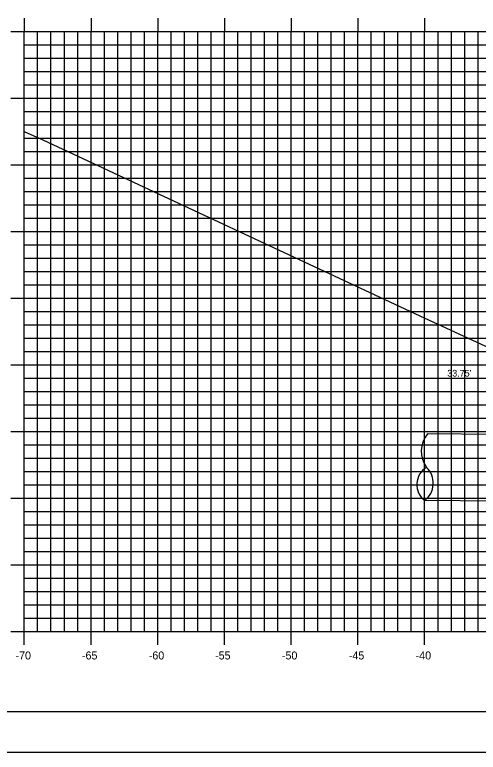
# Model space of a CAD drawing. Extents: x 1170543 to 1177585, y 609599 to 610623.
# Drawn here: x 1175064.6 to 1175099.3, y 609598.8 to 609654.1 of the extents above; entities that cross this region are included whole.
import ezdxf

# ---------------------------------------------------------------- set-up
doc = ezdxf.new("R2010")
doc.units = 0
for name, color, linetype in [('ANNOTATION', 7, 'Continuous'), ('BORDER', 7, 'Continuous'), ('D_Drainage_Text', 7, 'Continuous'), ('H_V ANNOTATION', 7, 'Continuous'), ('MAJOR', 7, 'Continuous'), ('MINOR', 7, 'Continuous'), ('PLOT BOUNDARY', 7, 'Continuous'), ('S_Roadway_Centerline', 7, 'Continuous')]:
    doc.layers.add(name, color=color, linetype=linetype)

msp = doc.modelspace()

# ---------------------------------------------------------------- linework, layer by layer
at = {"layer": 'BORDER'}
msp.add_line((1175060.313, 609601.872), (1175220.313, 609601.872), dxfattribs=at)
at = {"layer": 'D_Drainage_Text'}
for p, q in [((1175111.993, 609622.527), (1175095.525, 609622.687)), ((1175111.945, 609617.527), (1175095.318, 609617.689))]:
    msp.add_line(p, q, dxfattribs=at)
for centre, radius, start, end in [((1175097.136, 609621.381), 2.074, 140.9758, 215.5174), ((1175096.232, 609618.888), 1.508, 121.3337, 232.6687), ((1175094.316, 609618.989), 1.641, 307.6116, 46.3908)]:
    msp.add_arc(centre, radius, start, end, dxfattribs=at)
at = {"layer": 'MAJOR'}
for p, q in [((1175065.313, 609653.874), (1175065.313, 609652.872)), ((1175070.313, 609653.874), (1175070.313, 609652.872)), ((1175075.313, 609653.874), (1175075.313, 609652.872)), ((1175080.313, 609653.874), (1175080.313, 609652.872)), ((1175085.313, 609653.874), (1175085.313, 609652.872)), ((1175090.313, 609653.874), (1175090.313, 609652.872)), ((1175095.313, 609653.874), (1175095.313, 609652.872)), ((1175064.311, 609652.872), (1175065.313, 609652.872)), ((1175065.313, 609652.872), (1175205.313, 609652.872)), ((1175065.313, 609607.872), (1175065.313, 609652.872)), ((1175065.313, 609607.872), (1175065.313, 609652.872)), ((1175065.313, 609652.872), (1175205.313, 609652.872)), ((1175070.313, 609607.872), (1175070.313, 609652.872)), ((1175075.313, 609607.872), (1175075.313, 609652.872)), ((1175080.313, 609607.872), (1175080.313, 609652.872)), ((1175085.313, 609607.872), (1175085.313, 609652.872)), ((1175090.313, 609607.872), (1175090.313, 609652.872)), ((1175095.313, 609607.872), (1175095.313, 609652.872)), ((1175064.311, 609647.872), (1175065.313, 609647.872)), ((1175065.313, 609647.872), (1175205.313, 609647.872)), ((1175064.311, 609642.872), (1175065.313, 609642.872)), ((1175065.313, 609642.872), (1175205.313, 609642.872)), ((1175064.311, 609637.872), (1175065.313, 609637.872)), ((1175065.313, 609637.872), (1175205.313, 609637.872)), ((1175064.311, 609632.872), (1175065.313, 609632.872)), ((1175065.313, 609632.872), (1175205.313, 609632.872)), ((1175064.311, 609627.872), (1175065.313, 609627.872)), ((1175065.313, 609627.872), (1175205.313, 609627.872)), ((1175064.311, 609622.872), (1175065.313, 609622.872)), ((1175065.313, 609622.872), (1175205.313, 609622.872)), ((1175064.311, 609617.872), (1175065.313, 609617.872)), ((1175065.313, 609617.872), (1175205.313, 609617.872)), ((1175064.311, 609612.872), (1175065.313, 609612.872)), ((1175065.313, 609612.872), (1175205.313, 609612.872)), ((1175064.311, 609607.872), (1175065.313, 609607.872)), ((1175065.313, 609607.872), (1175205.313, 609607.872)), ((1175065.313, 609607.872), (1175205.313, 609607.872)), ((1175065.313, 609606.87), (1175065.313, 609607.872)), ((1175070.313, 609606.87), (1175070.313, 609607.872)), ((1175075.313, 609606.87), (1175075.313, 609607.872)), ((1175080.313, 609606.87), (1175080.313, 609607.872)), ((1175085.313, 609606.87), (1175085.313, 609607.872)), ((1175090.313, 609606.87), (1175090.313, 609607.872)), ((1175095.313, 609606.87), (1175095.313, 609607.872))]:
    msp.add_line(p, q, dxfattribs=at)
at = {"layer": 'MINOR'}
for p, q in [((1175066.313, 609607.872), (1175066.313, 609652.872)), ((1175067.313, 609607.872), (1175067.313, 609652.872)), ((1175068.313, 609607.872), (1175068.313, 609652.872)), ((1175069.313, 609607.872), (1175069.313, 609652.872)), ((1175071.313, 609607.872), (1175071.313, 609652.872)), ((1175072.313, 609607.872), (1175072.313, 609652.872)), ((1175073.313, 609607.872), (1175073.313, 609652.872)), ((1175074.313, 609607.872), (1175074.313, 609652.872)), ((1175076.313, 609607.872), (1175076.313, 609652.872)), ((1175077.313, 609607.872), (1175077.313, 609652.872)), ((1175078.313, 609607.872), (1175078.313, 609652.872)), ((1175079.313, 609607.872), (1175079.313, 609652.872)), ((1175081.313, 609607.872), (1175081.313, 609652.872)), ((1175082.313, 609607.872), (1175082.313, 609652.872)), ((1175083.313, 609607.872), (1175083.313, 609652.872)), ((1175084.313, 609607.872), (1175084.313, 609652.872)), ((1175086.313, 609607.872), (1175086.313, 609652.872)), ((1175087.313, 609607.872), (1175087.313, 609652.872)), ((1175088.313, 609607.872), (1175088.313, 609652.872)), ((1175089.313, 609607.872), (1175089.313, 609652.872)), ((1175091.313, 609607.872), (1175091.313, 609652.872)), ((1175092.313, 609607.872), (1175092.313, 609652.872)), ((1175093.313, 609607.872), (1175093.313, 609652.872)), ((1175094.313, 609607.872), (1175094.313, 609652.872)), ((1175096.313, 609607.872), (1175096.313, 609652.872)), ((1175097.313, 609607.872), (1175097.313, 609652.872)), ((1175098.313, 609607.872), (1175098.313, 609652.872)), ((1175099.313, 609607.872), (1175099.313, 609652.872)), ((1175065.313, 609651.872), (1175205.313, 609651.872)), ((1175065.313, 609651.872), (1175066.315, 609651.872)), ((1175065.313, 609650.872), (1175205.313, 609650.872)), ((1175065.313, 609650.872), (1175066.315, 609650.872)), ((1175065.313, 609649.872), (1175205.313, 609649.872)), ((1175065.313, 609649.872), (1175066.315, 609649.872)), ((1175065.313, 609648.872), (1175205.313, 609648.872)), ((1175065.313, 609648.872), (1175066.315, 609648.872)), ((1175065.313, 609646.872), (1175205.313, 609646.872)), ((1175065.313, 609646.872), (1175066.315, 609646.872)), ((1175065.313, 609645.872), (1175205.313, 609645.872)), ((1175065.313, 609645.872), (1175066.315, 609645.872)), ((1175065.313, 609644.872), (1175205.313, 609644.872)), ((1175065.313, 609644.872), (1175066.315, 609644.872)), ((1175065.313, 609643.872), (1175205.313, 609643.872)), ((1175065.313, 609643.872), (1175066.315, 609643.872)), ((1175065.313, 609641.872), (1175205.313, 609641.872)), ((1175065.313, 609641.872), (1175066.315, 609641.872)), ((1175065.313, 609640.872), (1175205.313, 609640.872)), ((1175065.313, 609640.872), (1175066.315, 609640.872)), ((1175065.313, 609639.872), (1175205.313, 609639.872)), ((1175065.313, 609639.872), (1175066.315, 609639.872)), ((1175065.313, 609638.872), (1175205.313, 609638.872)), ((1175065.313, 609638.872), (1175066.315, 609638.872)), ((1175065.313, 609636.872), (1175205.313, 609636.872)), ((1175065.313, 609636.872), (1175066.315, 609636.872)), ((1175065.313, 609635.872), (1175205.313, 609635.872)), ((1175065.313, 609635.872), (1175066.315, 609635.872)), ((1175065.313, 609634.872), (1175205.313, 609634.872)), ((1175065.313, 609634.872), (1175066.315, 609634.872)), ((1175065.313, 609633.872), (1175205.313, 609633.872)), ((1175065.313, 609633.872), (1175066.315, 609633.872)), ((1175065.313, 609631.872), (1175205.313, 609631.872)), ((1175065.313, 609631.872), (1175066.315, 609631.872)), ((1175065.313, 609630.872), (1175205.313, 609630.872)), ((1175065.313, 609630.872), (1175066.315, 609630.872)), ((1175065.313, 609629.872), (1175205.313, 609629.872)), ((1175065.313, 609629.872), (1175066.315, 609629.872)), ((1175065.313, 609628.872), (1175205.313, 609628.872)), ((1175065.313, 609628.872), (1175066.315, 609628.872)), ((1175065.313, 609626.872), (1175205.313, 609626.872)), ((1175065.313, 609626.872), (1175066.315, 609626.872)), ((1175065.313, 609625.872), (1175205.313, 609625.872)), ((1175065.313, 609625.872), (1175066.315, 609625.872)), ((1175065.313, 609624.872), (1175205.313, 609624.872)), ((1175065.313, 609624.872), (1175066.315, 609624.872)), ((1175065.313, 609623.872), (1175205.313, 609623.872)), ((1175065.313, 609623.872), (1175066.315, 609623.872)), ((1175065.313, 609621.872), (1175205.313, 609621.872)), ((1175065.313, 609621.872), (1175066.315, 609621.872)), ((1175065.313, 609620.872), (1175205.313, 609620.872)), ((1175065.313, 609620.872), (1175066.315, 609620.872)), ((1175065.313, 609619.872), (1175205.313, 609619.872)), ((1175065.313, 609619.872), (1175066.315, 609619.872)), ((1175065.313, 609618.872), (1175205.313, 609618.872)), ((1175065.313, 609618.872), (1175066.315, 609618.872)), ((1175065.313, 609616.872), (1175205.313, 609616.872)), ((1175065.313, 609616.872), (1175066.315, 609616.872)), ((1175065.313, 609615.872), (1175205.313, 609615.872)), ((1175065.313, 609615.872), (1175066.315, 609615.872)), ((1175065.313, 609614.872), (1175205.313, 609614.872)), ((1175065.313, 609614.872), (1175066.315, 609614.872)), ((1175065.313, 609613.872), (1175205.313, 609613.872)), ((1175065.313, 609613.872), (1175066.315, 609613.872)), ((1175065.313, 609611.872), (1175205.313, 609611.872)), ((1175065.313, 609611.872), (1175066.315, 609611.872)), ((1175065.313, 609610.872), (1175205.313, 609610.872)), ((1175065.313, 609610.872), (1175066.315, 609610.872)), ((1175065.313, 609609.872), (1175205.313, 609609.872)), ((1175065.313, 609609.872), (1175066.315, 609609.872)), ((1175065.313, 609608.872), (1175205.313, 609608.872)), ((1175065.313, 609608.872), (1175066.315, 609608.872))]:
    msp.add_line(p, q, dxfattribs=at)
at = {"layer": 'PLOT BOUNDARY'}
msp.add_lwpolyline([(1175052.22, 609598.813), (1175222.22, 609598.813), (1175222.22, 609708.813), (1175052.22, 609708.813)], close=True, dxfattribs=at)
at = {"layer": 'S_Roadway_Centerline'}
msp.add_lwpolyline([(1175065.313, 609645.364), (1175066.71, 609644.728), (1175094.949, 609631.538), (1175099.221, 609629.567), (1175108.065, 609625.487), (1175108.105, 609625.801), (1175108.115, 609625.79), (1175108.115, 609625.79), (1175118.148, 609630.814), (1175118.68, 609631.08), (1175119.215, 609631.348), (1175127.158, 609635.326), (1175127.269, 609635.381), (1175129.857, 609636.677), (1175132.804, 609636.751), (1175132.882, 609636.753), (1175133.28, 609636.739), (1175142.147, 609636.432), (1175142.15, 609636.432), (1175142.153, 609636.431), (1175148.742, 609636.203), (1175149.036, 609636.193), (1175164.221, 609635.667)], dxfattribs=at)

# ---------------------------------------------------------------- texts
at = {"layer": 'ANNOTATION'}
msp.add_text("33.75'", height=0.5, dxfattribs=at).set_placement((1175097.01, 609626.988))
at = {"layer": 'H_V ANNOTATION'}
for s, p in [('-70', (1175064.655, 609605.772)), ('-65', (1175069.631, 609605.772)), ('-60', (1175074.639, 609605.772)), ('-55', (1175079.609, 609605.772)), ('-50', (1175084.617, 609605.772)), ('-45', (1175089.631, 609605.772)), ('-40', (1175094.639, 609605.772))]:
    msp.add_text(s, height=0.6, dxfattribs=at).set_placement(p)

doc.saveas('drawing.dxf')
